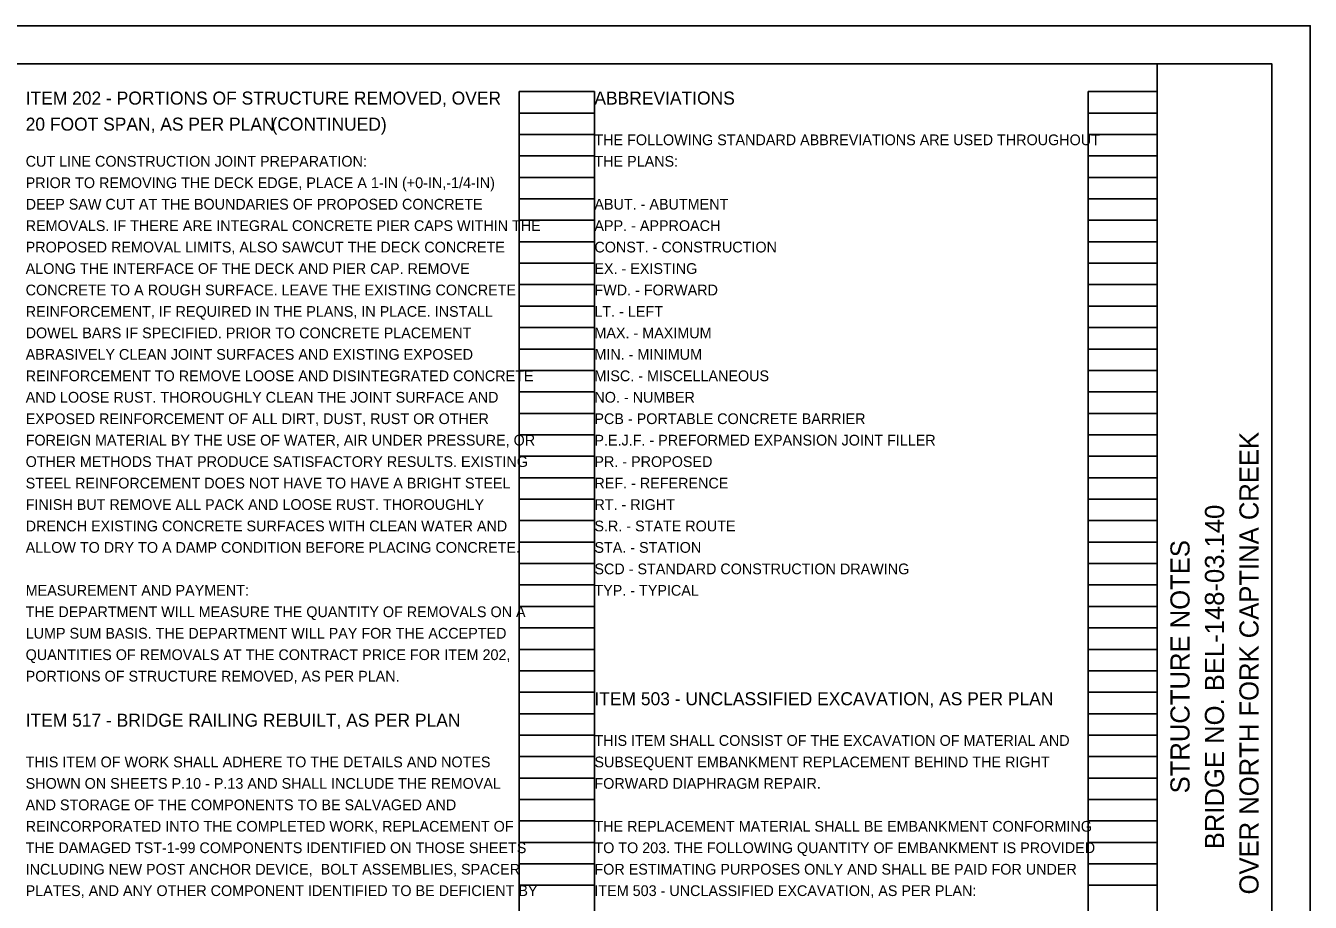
# Model space of a CAD drawing. Extents: x -16.5 to 61.9, y -20 to 22.7.
# Drawn here: x 17.24 to 34, y 10.56 to 22 of the extents above; entities that cross this region are included whole.
import ezdxf

# ---------------------------------------------------------------- set-up
doc = ezdxf.new("R2010")
doc.units = 0
for name, color, linetype in [('SH_Border', 7, 'Continuous'), ('SH_Cut_Line', 7, 'Continuous'), ('SH_Data', 7, 'Continuous'), ('SH_Text', 7, 'Continuous')]:
    doc.layers.add(name, color=color, linetype=linetype)

msp = doc.modelspace()

# ---------------------------------------------------------------- linework, layer by layer
at = {"layer": 'SH_Border'}
msp.add_line((32, 0.5), (32, 21.5), dxfattribs=at)
msp.add_lwpolyline([(1.5, 21.5), (33.5, 21.5), (33.5, 0.5), (1.5, 0.5)], close=True, dxfattribs=at)
at = {"layer": 'SH_Cut_Line'}
msp.add_lwpolyline([(0, 0), (34, 0), (34, 22), (0, 22)], close=True, dxfattribs=at)
at = {"layer": 'SH_Data'}
for p, q in [((23.68, 0.98), (23.68, 21.14)), ((23.68, 21.14), (24.66, 21.14)), ((24.66, 0.98), (24.66, 21.14)), ((31.1, 0.98), (31.1, 21.14)), ((31.1, 21.14), (32, 21.14)), ((32, 0.98), (32, 21.14)), ((23.68, 20.86), (24.66, 20.86)), ((31.1, 20.86), (32, 20.86)), ((23.68, 20.58), (24.66, 20.58)), ((31.1, 20.58), (32, 20.58)), ((23.68, 20.3), (24.66, 20.3)), ((31.1, 20.3), (32, 20.3)), ((23.68, 20.02), (24.66, 20.02)), ((31.1, 20.02), (32, 20.02)), ((23.68, 19.74), (24.66, 19.74)), ((31.1, 19.74), (32, 19.74)), ((23.68, 19.46), (24.66, 19.46)), ((31.1, 19.46), (32, 19.46)), ((23.68, 19.18), (24.66, 19.18)), ((31.1, 19.18), (32, 19.18)), ((23.68, 18.9), (24.66, 18.9)), ((31.1, 18.9), (32, 18.9)), ((23.68, 18.62), (24.66, 18.62)), ((31.1, 18.62), (32, 18.62)), ((23.68, 18.34), (24.66, 18.34)), ((31.1, 18.34), (32, 18.34)), ((23.68, 18.06), (24.66, 18.06)), ((31.1, 18.06), (32, 18.06)), ((23.68, 17.78), (24.66, 17.78)), ((31.1, 17.78), (32, 17.78)), ((23.68, 17.5), (24.66, 17.5)), ((31.1, 17.5), (32, 17.5)), ((23.68, 17.22), (24.66, 17.22)), ((31.1, 17.22), (32, 17.22)), ((23.68, 16.94), (24.66, 16.94)), ((31.1, 16.94), (32, 16.94)), ((23.68, 16.66), (24.66, 16.66)), ((31.1, 16.66), (32, 16.66)), ((23.68, 16.38), (24.66, 16.38)), ((31.1, 16.38), (32, 16.38)), ((23.68, 16.1), (24.66, 16.1)), ((31.1, 16.1), (32, 16.1)), ((23.68, 15.82), (24.66, 15.82)), ((31.1, 15.82), (32, 15.82)), ((23.68, 15.54), (24.66, 15.54)), ((31.1, 15.54), (32, 15.54)), ((23.68, 15.26), (24.66, 15.26)), ((31.1, 15.26), (32, 15.26)), ((23.68, 14.98), (24.66, 14.98)), ((31.1, 14.98), (32, 14.98)), ((23.68, 14.7), (24.66, 14.7)), ((31.1, 14.7), (32, 14.7)), ((23.68, 14.42), (24.66, 14.42)), ((31.1, 14.42), (32, 14.42)), ((23.68, 14.14), (24.66, 14.14)), ((31.1, 14.14), (32, 14.14)), ((23.68, 13.86), (24.66, 13.86)), ((31.1, 13.86), (32, 13.86)), ((23.68, 13.58), (24.66, 13.58)), ((31.1, 13.58), (32, 13.58)), ((23.68, 13.3), (24.66, 13.3)), ((31.1, 13.3), (32, 13.3)), ((23.68, 13.02), (24.66, 13.02)), ((31.1, 13.02), (32, 13.02)), ((23.68, 12.74), (24.66, 12.74)), ((31.1, 12.74), (32, 12.74)), ((23.68, 12.46), (24.66, 12.46)), ((31.1, 12.46), (32, 12.46)), ((23.68, 12.18), (24.66, 12.18)), ((31.1, 12.18), (32, 12.18)), ((23.68, 11.9), (24.66, 11.9)), ((31.1, 11.9), (32, 11.9)), ((23.68, 11.62), (24.66, 11.62)), ((31.1, 11.62), (32, 11.62)), ((23.68, 11.34), (24.66, 11.34)), ((31.1, 11.34), (32, 11.34)), ((23.68, 11.06), (24.66, 11.06)), ((31.1, 11.06), (32, 11.06)), ((23.68, 10.78), (24.66, 10.78)), ((31.1, 10.78), (32, 10.78))]:
    msp.add_line(p, q, dxfattribs=at)

# ---------------------------------------------------------------- texts
for s, p in [('OVER NORTH FORK CAPTINA CREEK', (33.325, 10.661)), ('BRIDGE NO. BEL-148-03.140', (32.875, 11.251)), ('STRUCTURE NOTES', (32.425, 11.98))]:
    msp.add_text(s, height=0.25, rotation=90, dxfattribs=at).set_placement(p)
at = {"layer": 'SH_Text'}
for s, height, p in [('ITEM 202 - PORTIONS OF STRUCTURE REMOVED, OVER ', 0.17, (17.24, 20.97)), ('ABBREVIATIONS', 0.17, (24.66, 20.97)), ('20 FOOT SPAN, AS PER PLAN', 0.17, (17.24, 20.63)), (' (CONTINUED)', 0.17, (20.384, 20.63)), ('THE FOLLOWING STANDARD ABBREVIATIONS ARE USED THROUGHOUT ', 0.14, (24.66, 20.44)), ('CUT LINE CONSTRUCTION JOINT PREPARATION: ', 0.14, (17.24, 20.16)), ('THE PLANS:', 0.14, (24.66, 20.16)), ('PRIOR TO REMOVING THE DECK EDGE, PLACE A 1-IN (+0-IN,-1/4-IN) ', 0.14, (17.24, 19.88)), ('DEEP SAW CUT AT THE BOUNDARIES OF PROPOSED CONCRETE ', 0.14, (17.24, 19.6)), ('ABUT. - ABUTMENT', 0.14, (24.66, 19.6)), ('REMOVALS. IF THERE ARE INTEGRAL CONCRETE PIER CAPS WITHIN THE ', 0.14, (17.24, 19.32)), ('APP. - APPROACH', 0.14, (24.66, 19.32)), ('PROPOSED REMOVAL LIMITS, ALSO SAWCUT THE DECK CONCRETE ', 0.14, (17.24, 19.04)), ('CONST. - CONSTRUCTION', 0.14, (24.66, 19.04)), ('ALONG THE INTERFACE OF THE DECK AND PIER CAP. REMOVE ', 0.14, (17.24, 18.76)), ('EX. - EXISTING', 0.14, (24.66, 18.76)), ('CONCRETE TO A ROUGH SURFACE. LEAVE THE EXISTING CONCRETE ', 0.14, (17.24, 18.48)), ('FWD. - FORWARD', 0.14, (24.66, 18.48)), ('REINFORCEMENT, IF REQUIRED IN THE PLANS, IN PLACE. INSTALL ', 0.14, (17.24, 18.2)), ('LT. - LEFT', 0.14, (24.66, 18.2)), ('DOWEL BARS IF SPECIFIED. PRIOR TO CONCRETE PLACEMENT ', 0.14, (17.24, 17.92)), ('MAX. - MAXIMUM', 0.14, (24.66, 17.92)), ('ABRASIVELY CLEAN JOINT SURFACES AND EXISTING EXPOSED ', 0.14, (17.24, 17.64)), ('MIN. - MINIMUM', 0.14, (24.66, 17.64)), ('REINFORCEMENT TO REMOVE LOOSE AND DISINTEGRATED CONCRETE ', 0.14, (17.24, 17.36)), ('MISC. - MISCELLANEOUS', 0.14, (24.66, 17.36)), ('AND LOOSE RUST. THOROUGHLY CLEAN THE JOINT SURFACE AND ', 0.14, (17.24, 17.08)), ('NO. - NUMBER', 0.14, (24.66, 17.08)), ('EXPOSED REINFORCEMENT OF ALL DIRT, DUST, RUST OR OTHER ', 0.14, (17.24, 16.8)), ('PCB - PORTABLE CONCRETE BARRIER', 0.14, (24.66, 16.8)), ('FOREIGN MATERIAL BY THE USE OF WATER, AIR UNDER PRESSURE, OR ', 0.14, (17.24, 16.52)), ('P.E.J.F. - PREFORMED EXPANSION JOINT FILLER', 0.14, (24.66, 16.52)), ('OTHER METHODS THAT PRODUCE SATISFACTORY RESULTS. EXISTING ', 0.14, (17.24, 16.24)), ('PR. - PROPOSED', 0.14, (24.66, 16.24)), ('STEEL REINFORCEMENT DOES NOT HAVE TO HAVE A BRIGHT STEEL ', 0.14, (17.24, 15.96)), ('REF. - REFERENCE', 0.14, (24.66, 15.96)), ('FINISH BUT REMOVE ALL PACK AND LOOSE RUST. THOROUGHLY ', 0.14, (17.24, 15.68)), ('RT. - RIGHT', 0.14, (24.66, 15.68)), ('DRENCH EXISTING CONCRETE SURFACES WITH CLEAN WATER AND ', 0.14, (17.24, 15.4)), ('S.R. - STATE ROUTE', 0.14, (24.66, 15.4)), ('ALLOW TO DRY TO A DAMP CONDITION BEFORE PLACING CONCRETE. ', 0.14, (17.24, 15.12)), ('STA. - STATION', 0.14, (24.66, 15.12)), ('SCD - STANDARD CONSTRUCTION DRAWING', 0.14, (24.66, 14.84)), ('MEASUREMENT AND PAYMENT:', 0.14, (17.24, 14.56)), ('TYP. - TYPICAL', 0.14, (24.66, 14.56)), ('THE DEPARTMENT WILL MEASURE THE QUANTITY OF REMOVALS ON A ', 0.14, (17.24, 14.28)), ('LUMP SUM BASIS. THE DEPARTMENT WILL PAY FOR THE ACCEPTED ', 0.14, (17.24, 14)), ('QUANTITIES OF REMOVALS AT THE CONTRACT PRICE FOR ITEM 202, ', 0.14, (17.24, 13.72)), ('PORTIONS OF STRUCTURE REMOVED, AS PER PLAN.', 0.14, (17.24, 13.44)), ('ITEM 503 - UNCLASSIFIED EXCAVATION, AS PER PLAN', 0.17, (24.66, 13.13)), ('ITEM 517 - BRIDGE RAILING REBUILT, AS PER PLAN', 0.17, (17.24, 12.85)), ('THIS ITEM SHALL CONSIST OF THE EXCAVATION OF MATERIAL AND ', 0.14, (24.66, 12.6)), ('THIS ITEM OF WORK SHALL ADHERE TO THE DETAILS AND NOTES ', 0.14, (17.24, 12.32)), ('SUBSEQUENT EMBANKMENT REPLACEMENT BEHIND THE RIGHT ', 0.14, (24.66, 12.32)), ('SHOWN ON SHEETS P.10 - P.13 AND SHALL INCLUDE THE REMOVAL ', 0.14, (17.24, 12.04)), ('FORWARD DIAPHRAGM REPAIR. ', 0.14, (24.66, 12.04)), ('AND STORAGE OF THE COMPONENTS TO BE SALVAGED AND ', 0.14, (17.24, 11.76)), ('REINCORPORATED INTO THE COMPLETED WORK, REPLACEMENT OF ', 0.14, (17.24, 11.48)), ('THE REPLACEMENT MATERIAL SHALL BE EMBANKMENT CONFORMING ', 0.14, (24.66, 11.48)), ('THE DAMAGED TST-1-99 COMPONENTS IDENTIFIED ON THOSE SHEETS ', 0.14, (17.24, 11.2)), ('TO TO 203. THE FOLLOWING QUANTITY OF EMBANKMENT IS PROVIDED ', 0.14, (24.66, 11.2)), ('INCLUDING NEW POST ANCHOR DEVICE,  BOLT ASSEMBLIES, SPACER ', 0.14, (17.24, 10.92)), ('FOR ESTIMATING PURPOSES ONLY AND SHALL BE PAID FOR UNDER ', 0.14, (24.66, 10.92)), ('PLATES, AND ANY OTHER COMPONENT IDENTIFIED TO BE DEFICIENT BY ', 0.14, (17.24, 10.64)), ('ITEM 503 - UNCLASSIFIED EXCAVATION, AS PER PLAN:               ', 0.14, (24.66, 10.64))]:
    msp.add_text(s, height=height, dxfattribs=at).set_placement(p)

doc.saveas('drawing.dxf')
